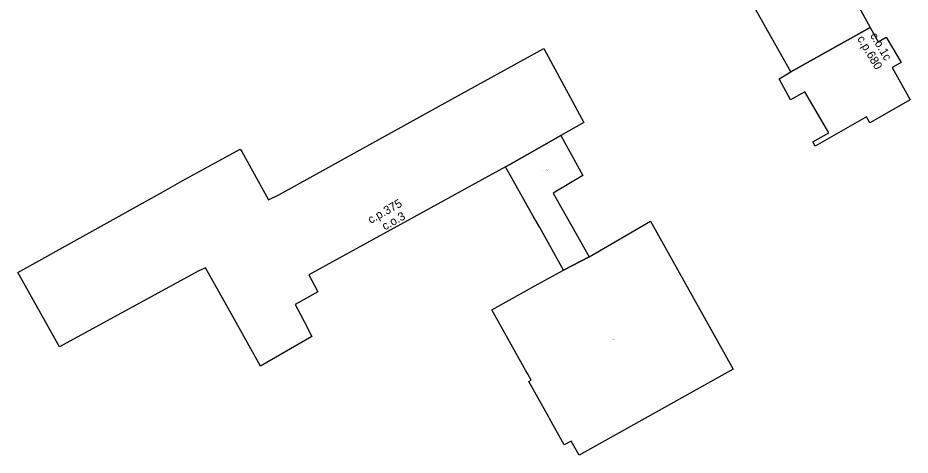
# Model space of a CAD drawing. Extents: x -600391 to -599491, y -1160176 to -1159402.
# Drawn here: x -600141.4 to -600035.8, y -1159723 to -1159671.2 of the extents above; entities that cross this region are included whole.
import ezdxf

# ---------------------------------------------------------------- set-up
doc = ezdxf.new("R2010")
doc.units = 0
for name, color, linetype in [('Level 10', 7, 'Continuous'), ('Level 12', 7, 'Continuous'), ('Level 24', 7, 'Continuous'), ('Level 25', 7, 'Continuous'), ('Level 61', 7, 'Continuous'), ('Level 62', 7, 'Continuous')]:
    doc.layers.add(name, color=color, linetype=linetype)

msp = doc.modelspace()

# ---------------------------------------------------------------- linework, layer by layer
at = {"layer": 'Level 61'}
for points in [[(-600045.75, -1159662.73), (-600040.52, -1159672.35)], [(-600049.89, -1159677.6), (-600055.29, -1159668.02)], [(-600049.89, -1159677.6), (-600040.52, -1159672.35)], [(-600040.52, -1159672.35), (-600049.89, -1159677.6)], [(-600040.52, -1159672.35), (-600039.55, -1159674.03)], [(-600039.55, -1159674.03), (-600038.62, -1159673.51)], [(-600038.62, -1159673.51), (-600036.86, -1159676.5)], [(-600091.62, -1159681.69), (-600079.17, -1159674.84)], [(-600079.17, -1159674.84), (-600074.42, -1159683.6)], [(-600036.86, -1159676.5), (-600037.9, -1159677.08)], [(-600051.28, -1159678.44), (-600049.89, -1159677.6)], [(-600037.9, -1159677.08), (-600035.78, -1159680.91)], [(-600049.96, -1159680.91), (-600051.28, -1159678.44)], [(-600048.24, -1159679.98), (-600049.96, -1159680.91)], [(-600045.42, -1159684.82), (-600048.24, -1159679.98)], [(-600110.54, -1159692.17), (-600091.62, -1159681.69)], [(-600035.78, -1159680.91), (-600040.57, -1159683.65)], [(-600040.95, -1159682.94), (-600047.02, -1159686.41)], [(-600040.57, -1159683.65), (-600040.95, -1159682.94)], [(-600074.42, -1159683.6), (-600077.14, -1159685.14)], [(-600047.29, -1159685.89), (-600045.42, -1159684.82)], [(-600077.14, -1159685.14), (-600083.2, -1159688.57)], [(-600083.2, -1159688.57), (-600077.14, -1159685.14)], [(-600077.14, -1159685.14), (-600074.53, -1159689.87)], [(-600047.02, -1159686.41), (-600047.29, -1159685.89)], [(-600119.36, -1159689.09), (-600115.12, -1159686.75)], [(-600115.12, -1159686.75), (-600114.93, -1159687.05)], [(-600114.93, -1159687.05), (-600111.75, -1159692.77)], [(-600122, -1159690.53), (-600119.36, -1159689.09)], [(-600083.69, -1159688.84), (-600106.97, -1159701.66)], [(-600083.2, -1159688.57), (-600083.69, -1159688.84)], [(-600083.69, -1159688.84), (-600083.2, -1159688.57)], [(-600080.41, -1159694.69), (-600083.69, -1159688.84)], [(-600074.53, -1159689.87), (-600078.07, -1159691.99)], [(-600124.19, -1159691.77), (-600122, -1159690.53)], [(-600141.44, -1159701.37), (-600124.19, -1159691.77)], [(-600111.75, -1159692.77), (-600110.54, -1159692.17)], [(-600078.07, -1159691.99), (-600073.78, -1159699.52)], [(-600079.65, -1159696.04), (-600080.41, -1159694.69)], [(-600073.78, -1159699.52), (-600066.52, -1159695.3)], [(-600066.52, -1159695.3), (-600056.72, -1159712.82)], [(-600076.82, -1159701.09), (-600079.65, -1159696.04)], [(-600073.78, -1159699.52), (-600076.82, -1159701.09)], [(-600076.82, -1159701.09), (-600073.78, -1159699.52)], [(-600119.23, -1159700.81), (-600120.07, -1159701.2)], [(-600116, -1159706.59), (-600119.23, -1159700.81)], [(-600141.29, -1159701.65), (-600141.44, -1159701.37)], [(-600136.5, -1159710.18), (-600141.29, -1159701.65)], [(-600120.07, -1159701.2), (-600136.5, -1159710.18)], [(-600106.97, -1159701.66), (-600105.91, -1159703.65)], [(-600078.99, -1159702.29), (-600076.82, -1159701.09)], [(-600085.33, -1159705.79), (-600079.86, -1159702.77)], [(-600079.86, -1159702.77), (-600078.99, -1159702.29)], [(-600105.91, -1159703.65), (-600108.61, -1159705.15)], [(-600108.61, -1159705.15), (-600107.99, -1159706.34)], [(-600081.27, -1159713.03), (-600085.33, -1159705.79)], [(-600112.72, -1159712.47), (-600116, -1159706.59)], [(-600107.99, -1159706.34), (-600107.55, -1159707.19)], [(-600107.55, -1159707.19), (-600106.62, -1159708.97)], [(-600106.62, -1159708.97), (-600112.72, -1159712.47)], [(-600081.09, -1159713.35), (-600081.27, -1159713.03)], [(-600080.65, -1159714.14), (-600081.09, -1159713.35)], [(-600056.72, -1159712.82), (-600074.97, -1159723.02)], [(-600080.92, -1159714.29), (-600080.65, -1159714.14)], [(-600078.58, -1159718.5), (-600080.92, -1159714.29)], [(-600078.48, -1159718.68), (-600078.58, -1159718.5)], [(-600076.75, -1159721.81), (-600078.48, -1159718.68)], [(-600075.92, -1159721.35), (-600076.75, -1159721.81)], [(-600074.97, -1159723.02), (-600075.92, -1159721.35)]]:
    msp.add_lwpolyline(points, dxfattribs=at)
at = {"layer": 'Level 62'}
for points in [[(-600055.29, -1159668.02), (-600045.75, -1159662.73), (-600040.52, -1159672.35), (-600049.89, -1159677.6), (-600055.29, -1159668.02)], [(-600049.89, -1159677.6), (-600040.52, -1159672.35), (-600039.55, -1159674.03), (-600038.62, -1159673.51), (-600036.86, -1159676.5), (-600037.9, -1159677.08), (-600035.78, -1159680.91), (-600040.57, -1159683.65), (-600040.95, -1159682.94), (-600047.02, -1159686.41), (-600047.29, -1159685.89), (-600045.42, -1159684.82), (-600048.24, -1159679.98), (-600049.96, -1159680.91), (-600051.28, -1159678.44), (-600049.89, -1159677.6)], [(-600083.69, -1159688.84), (-600106.97, -1159701.66), (-600105.91, -1159703.65), (-600108.61, -1159705.15), (-600107.99, -1159706.34), (-600107.55, -1159707.19), (-600106.62, -1159708.97), (-600112.72, -1159712.47), (-600116, -1159706.59), (-600119.23, -1159700.81), (-600120.07, -1159701.2), (-600136.5, -1159710.18), (-600141.29, -1159701.65), (-600141.44, -1159701.37), (-600124.19, -1159691.77), (-600122, -1159690.53), (-600119.36, -1159689.09), (-600115.12, -1159686.75), (-600114.93, -1159687.05), (-600111.75, -1159692.77), (-600110.54, -1159692.17), (-600091.62, -1159681.69), (-600079.17, -1159674.84), (-600074.42, -1159683.6), (-600077.14, -1159685.14), (-600083.2, -1159688.57), (-600083.69, -1159688.84)], [(-600083.69, -1159688.84), (-600083.2, -1159688.57), (-600077.14, -1159685.14), (-600074.53, -1159689.87), (-600078.07, -1159691.99), (-600073.78, -1159699.52), (-600076.82, -1159701.09), (-600079.65, -1159696.04), (-600080.41, -1159694.69), (-600083.69, -1159688.84)], [(-600073.78, -1159699.52), (-600066.52, -1159695.3), (-600056.72, -1159712.82), (-600074.97, -1159723.02), (-600075.92, -1159721.35), (-600076.75, -1159721.81), (-600078.48, -1159718.68), (-600078.58, -1159718.5), (-600080.92, -1159714.29), (-600080.65, -1159714.14), (-600081.09, -1159713.35), (-600081.27, -1159713.03), (-600085.33, -1159705.79), (-600079.86, -1159702.77), (-600078.99, -1159702.29), (-600076.82, -1159701.09), (-600073.78, -1159699.52)]]:
    msp.add_lwpolyline(points, dxfattribs=at)

# ---------------------------------------------------------------- texts
at = {"layer": 'Level 10'}
for s, rotation, p in [('c.o.1c', 300.4833, (-600040.56, -1159673.3)), ('c.o.3', 29.4208, (-600097.98, -1159696.41))]:
    msp.add_text(s, height=1, rotation=rotation, dxfattribs=at).set_placement(p)
at = {"layer": 'Level 12'}
for s, rotation, p in [('c.p.680', 300.4833, (-600042.09, -1159673.66)), ('c.p.375', 29.4208, (-600099.66, -1159695.63))]:
    msp.add_text(s, height=1, rotation=rotation, dxfattribs=at).set_placement(p)
at = {"layer": 'Level 24'}
msp.add_text('c.z.410', height=0.1, dxfattribs=at).set_placement((-600071.22, -1159709.38))
at = {"layer": 'Level 25'}
msp.add_text('c.pp.375_A', height=0.1, dxfattribs=at).set_placement((-600079.3, -1159689.3))

doc.saveas('drawing.dxf')
